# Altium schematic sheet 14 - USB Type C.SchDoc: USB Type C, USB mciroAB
size A3; PageSetup: Record=PageOptions¦CenterHorizontal=True¦CenterVertical=True¦PrintScale=0.70¦XCorrection=1.00¦YCorrection=1.00¦PrintKind=0¦BorderSize=5000000¦LeftOffset=0¦BottomOffset=0¦Orientation=2¦PaperLength=4200¦PaperWidth=2970¦Scale=100¦PaperSource=7¦PrintQuality=600¦MediaType=1¦DitherType=10¦PaperKind=A4¦PrintScaleMode=1; Author: Juan Anzola; SheetNumber: 14; SheetTotal: 20
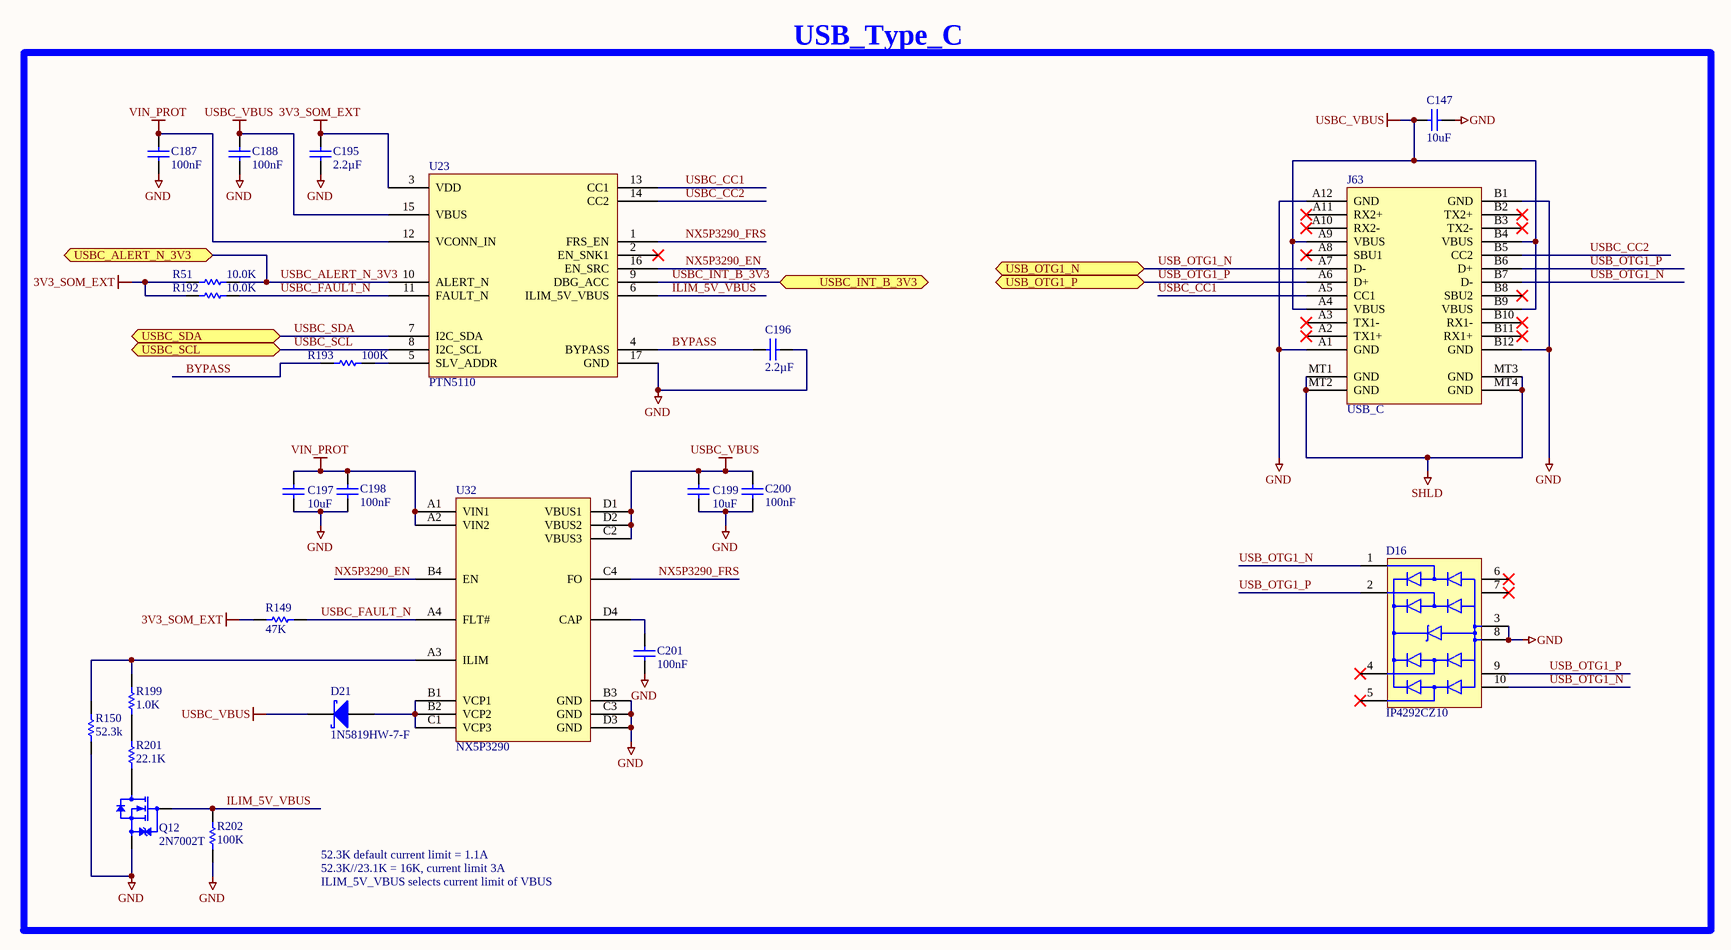
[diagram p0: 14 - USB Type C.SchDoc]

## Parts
C147  10uF  [CAPC1005X55N]
C187  100nF  [CAPC1005X55N]
C188  100nF  [CAPC1005X55N]
C195  2.2µF  [CAPC1005X55L]
C196  2.2µF  [CAPC1005X55L]
C197  10uF  [CAPC1005X55N]
C198  100nF  [CAPC1005X55N]
C199  10uF  [CAPC1005X55N]
C200  100nF  [CAPC1005X55N]
C201  100nF  [CAPC1005X55N]
D16  IP4292CZ10  [SON50P250X100X50-10N]
D21  1N5819HW-7-F  [SOD3716X135N]
J63  USB_C  [MOLEX_201267-0005]
Q12  2N7002T  [SOTFL50P160X80_GSD-3N]
R51  10.0K  [RESC1005X40N]
R149  47K  [RESC1005X40N]
R150  52.3k  [RESC1005X40N]
R192  10.0K  [RESC1005X40N]
R193  100K  [RESC1005X40N]
R199  1.0K  [RESC1005X40N]
R201  22.1K  [RESC1005X40N]
R202  100K  [RESC1005X40N]
U23  PTN5110  [QFN40P260X260X40-17T100X110N]
U32  NX5P3290  [BGA16N50P4X4_205X205X59B32N]

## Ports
USB_OTG1_N (bidir), USB_OTG1_P (bidir), USBC_ALERT_N_3V3 (bidir), USBC_INT_B_3V3 (bidir), USBC_SCL (bidir), USBC_SDA (bidir)

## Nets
3V3_SOM_EXT: C195.2 R51.1 R149.1 R192.1 U23.3(VDD)
GND: C147.1 C187.1 C188.1 C195.1 C196.1 C197.1 C198.1 C199.1 C200.1 C201.1 D16.3(GND) D16.8(GND) J63.A1(GND) J63.A12(GND) J63.B1(GND) J63.B12(GND) Q12.S R150.1 R202.1 U23.17(GND) U32.B3(GND) U32.C3(GND) U32.D3(GND)
SHLD: J63.MT1(GND) J63.MT2(GND) J63.MT3(GND) J63.MT4(GND)
USBC_VBUS: C147.2 C188.2 C199.2 C200.2 D21.K J63.A4(VBUS) J63.A9(VBUS) J63.B4(VBUS) J63.B9(VBUS) U23.15(VBUS) U32.C2(VBUS3) U32.D1(VBUS1) U32.D2(VBUS2)
VIN_PROT: C187.2 C197.2 C198.2 U23.12(VCONN_IN) U32.A1(VIN1) U32.A2(VIN2)
BYPASS: C196.2 R193.1 U23.4(BYPASS)
ILIM_5V_VBUS: Q12.G R202.2 U23.6(ILIM_5V_VBUS)
NX5P3290_EN: U23.16(EN_SRC) U32.B4(EN)
NX5P3290_FRS: U23.1(FRS_EN) U32.C4(FO)
USB_OTG1_N: D16.1(CH1) D16.10(NC) J63.A7(D-) J63.B7(D-) ; port USB_OTG1_N
USB_OTG1_P: D16.2(CH2) D16.9(NC) J63.A6(D+) J63.B6(D+) ; port USB_OTG1_P
USBC_ALERT_N_3V3: R51.2 U23.10(ALERT_N) ; port USBC_ALERT_N_3V3
USBC_CC1: J63.A5(CC1) U23.13(CC1)
USBC_CC2: J63.B5(CC2) U23.14(CC2)
USBC_FAULT_N: R149.2 R192.2 U23.11(FAULT_N) U32.A4(FLT#)
USBC_INT_B_3V3: U23.9(DBG_ACC) ; port USBC_INT_B_3V3
USBC_SCL: U23.8(I2C_SCL) ; port USBC_SCL
USBC_SDA: U23.7(I2C_SDA) ; port USBC_SDA
NetC201_2: C201.2 U32.D4(CAP)
NetD21_A: D21.A U32.B1(VCP1) U32.B2(VCP2) U32.C1(VCP3)
NetQ12_D: Q12.D R201.1
NetR150_2: R150.2 R199.2 U32.A3(ILIM)
NetR193_2: R193.2 U23.5(SLV_ADDR)
NetR199_1: R199.1 R201.2

Not connected (* = marked no-connect by the designer): D16 4(CH3)* 5(CH4)* 6(NC)* 7(NC)*; J63 A2(TX1+)* A3(TX1-)* A8(SBU1)* A10(RX2-)* A11(RX2+)* B2(TX2+)* B3(TX2-)* B8(SBU2)* B10(RX1-)* B11(RX1+)*; U23 2(EN_SNK1)*

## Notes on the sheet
- USB_Type_C
- 52.3K default current limit = 1.1A
- 52.3K//23.1K = 16K, current limit 3A
- ILIM_5V_VBUS selects current limit of VBUS

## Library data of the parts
C147 C197 C199 = 1001168: CAP CER 10UF 10V 20% X5R 0402; Part_Type: Capacitor; Manufacturer: Samsung; Manufacturer_Part_Number: CL05A106MP5NUNC; Digi_PN: 14050689; Component_Life_Cycle_State: Reviewed; Area: 0.95; Project: CCWMX6_SBC board
C187 C188 C198 C200 C201 = 1000006: CAP 100nF 16V 10% X7R 0402; Part_Type: Capacitor; Manufacturer: Murata; Manufacturer_Part_Number: GRM155R71C104KA88D; Component_Life_Cycle_State: CAD Reviewed; Area: 0.95; Project: KITT; Tolerance: 10; Digi_PN: 14050552
C195 C196 = 1000970: CAP CER 2.2UF 6.3V 20% X5R 0402; Part_Type: Capacitor; Manufacturer: TDK Corporation; Manufacturer_Part_Number: C1005X5R0J225M050BC; Manufacturer_Alt_1: Taiyo Yuden; Manufacturer_Alt_1_Part_Number: JMK105BJ225MV-F; Note: 14050756 = Digi No. for GE WDNU; Digi_PN: 14050493; Component_Life_Cycle_State: Reviewed; Area: 0.5; Project: ConnectCore i.MX6 module; Tolerance: 20
D16 = 1002593: TVS DIODE 5.5V 4V 10DFN; Part_Type: Circuit Protection; Manufacturer: Phillips NXP; Digi_PN: 17000143; Component_Life_Cycle_State: Created; Area: 7,24; Project: DIGI CC8X SOM
D21 = 1000231: DIODE SCHOTTKY 40V 1A SOD123; Part_Type: Diodes; Manufacturer: Diodes, Inc.; Digi_PN: 17000146; Component_Life_Cycle_State: Proven; Area: 8.28; Project: Adjustable Foundation
J63 = 1002675: USB 3.1 SHIELDED I/O RECP TYPE C GEN2; Part_Type: Connector; Manufacturer: Molex; Manufacturer_Part_Number: 201267-0005; Digi_PN: 18000775; Component_Life_Cycle_State: Created; Area: 86.57; Project: DIGI CC8X SOM
Q12 = 1000715: MOSFET N-CH 60V 115MA SOT-523F; Part_Type: Transistor; Manufacturer: Fairchild Semiconductor; Digi_PN: 17050797; Component_Life_Cycle_State: CAD Reviewed; Area: 3.06; Project: SmartMeter2; Note: 17050841 = Digi No. for GE WDNU
R51 R192 = 1000537: RES 10.0K OHM 1/10W 1% 0402 SMD; Part_Type: Resistor; Manufacturer: Panasonic - ECG; Manufacturer_Part_Number: ERJ-2RKF1002X; Component_Life_Cycle_State: CAD Reviewed; Area: 0.95; Project: KITT; Power_WV_SRF: 100; Digi_PN: 13051084
R149 = 1001155: RES 47.0K OHM 1/16W 1% 0402 SMD; Part_Type: Resistor; Manufacturer: Vishay Dale; Manufacturer_Part_Number: CRCW040247K0FKED; Digi_PN: 13050646; Component_Life_Cycle_State: Reviewed; Area: 0,95; Project: CCWMX6_SBC board
R150 = 1000170: RES 52.3K OHM 1/10W 1% 0402 SMD; Part_Type: Resistor; Manufacturer: Panasonic - ECG; Manufacturer_Part_Number: ERJ-2RKF5232X; Digi_PN: 13000085; Component_Life_Cycle_State: Reviewed; Area: 0.95; Project: USB UART to USB Transceiver; Power_WV_SRF: 10
R193 = 1000480: RES 100K OHM 1/10W 1% 0402 SMD; Part_Type: Resistor; Manufacturer: Panasonic - ECG; Manufacturer_Part_Number: ERJ-2RKF1003X; Digi_PN: 13051063; Component_Life_Cycle_State: CAD Reviewed; Area: 0,95; Power_WV_SRF: 100
R199 = 1000079: RES 1.00K OHM 1/10W 1% 0402 SMD; Part_Type: Resistor; Manufacturer: Panasonic - ECG; Manufacturer_Part_Number: ERJ-2RKF1001X; Digi_PN: 13051085; Component_Life_Cycle_State: Proven; Area: 0,95; Project: Adjustable Foundation; Power_WV_SRF: 10
R201 = 1001149: RES 22.1K OHM 1/16W 1% 0402 SMD; Part_Type: Resistor; Manufacturer: Vishay Dale; Manufacturer_Part_Number: CRCW040222K1FKED; Digi_PN: 13050450; Component_Life_Cycle_State: Reviewed; Area: 0,95; Project: CCWMX6_SBC board; Power_WV_SRF: 0,063; Tolerance: ±100ppm/°C
R202 = 1000480: RES 100K OHM 1/10W 1% 0402 SMD; Part_Type: Resistor; Manufacturer: Panasonic - ECG; Manufacturer_Part_Number: ERJ-2RKF1003X; Digi_PN: 13051063; Component_Life_Cycle_State: CAD Reviewed; Area: 0.95; Project: KITT; Power_WV_SRF: 100
U23 = 1002585: IC USB PD TCPC PHY HX2QFN16; Manufacturer: NXP Semiconductors; Digi_PN: 16000125; Component_Life_Cycle_State: Reviewed; Area: 14.75; Project: DIGI CC8X SOM
U32 = 1002586: IC USB POWER SWITCH 16WLCSP; Manufacturer: NXP Semiconductors; Digi_PN: 16000126; Component_Life_Cycle_State: Reviewed; Area: 6.76; Project: DIGI CC8X SOM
